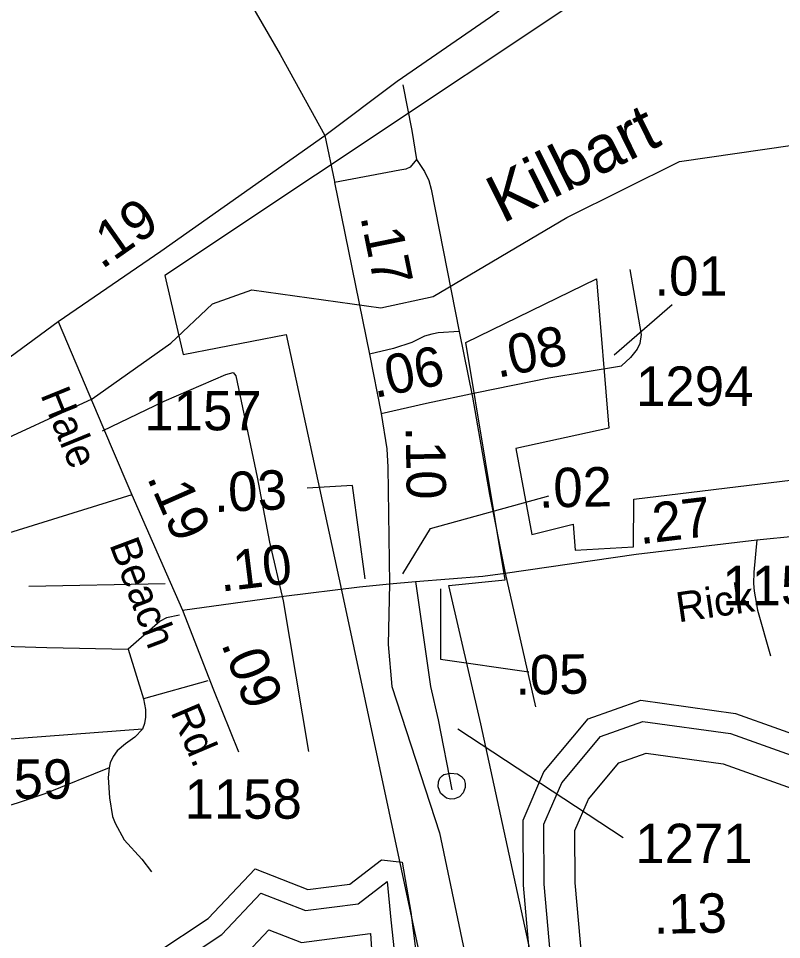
# Model space of a CAD drawing. Extents: x 2104537 to 2336408, y 34176 to 229611.
# Drawn here: x 2168604 to 2171023, y 54016 to 56935 of the extents above; entities that cross this region are included whole.
import ezdxf

# ---------------------------------------------------------------- set-up
doc = ezdxf.new("R2010")
doc.units = 0
for name, color, linetype in [('Exist Boundary Political City Limit New', 7, 'Continuous'), ('Exist Hydrographic Buffer Line', 7, 'Continuous'), ('Exist Hydrographic Creek Single Shore', 7, 'Continuous'), ('Exist Road Non-System Type 51', 7, 'Continuous'), ('Exist Road Primary NC Attributed', 7, 'Continuous'), ('Exist Road Primary NC Mileage Hundredths English Label', 7, 'Continuous'), ('Exist Road Secondary Mileage Hundredths English Label', 7, 'Continuous'), ('Exist Road Secondary Type 51 Attributed', 7, 'Continuous'), ('Exist Road Secondary Type 51 Label', 7, 'Continuous'), ('Exist Road Secondary Type 51 Number Label', 7, 'Continuous'), ('Map Preparation Boundary City Limit Buffer Line', 7, 'Continuous'), ('Old_Level_32', 7, 'Continuous')]:
    doc.layers.add(name, color=color, linetype=linetype)

msp = doc.modelspace()

# ---------------------------------------------------------------- linework, layer by layer
at = {"layer": 'Exist Boundary Political City Limit New'}
msp.add_lwpolyline([(2176257.8, 54846.6), (2173854.8, 54184.7), (2170314, 53571.9), (2170069.8, 54698.9), (2169968, 55137.6), (2170146.2, 55155.3), (2170021.5, 55907.7), (2170435.5, 56110), (2170474.8, 55636), (2170179.8, 55571.6), (2170231.5, 55299.3), (2170362.5, 55332.5), (2170368.8, 55249.4), (2170553.8, 55259.8), (2170554, 55411.4), (2171311.8, 55503.1), (2170974.8, 57391.3), (2169068.2, 56119.6), (2169126, 55869.2), (2169452.2, 55932.9), (2169628, 55123.1), (2169966.8, 53537.6)], dxfattribs=at)
at = {"layer": 'Exist Hydrographic Buffer Line'}
for points in [[(2170318.6, 53644.1), (2170270, 54190.6), (2170269.1, 54380.8), (2170325.9, 54512.4), (2170448.3, 54659.2), (2170583.2, 54707), (2170860.7, 54668.3), (2171275.3, 54520.6), (2171475.4, 54528), (2172014.2, 54766.4), (2172225.3, 54765.3), (2172465.8, 54706.7), (2172678.2, 54748.2), (2172795.6, 54838.6), (2172763.6, 55066.9), (2172705, 55237.7), (2172704, 55437.6), (2172771.6, 55612.9), (2172986, 55968.3), (2173064.5, 56033.8), (2173115.1, 56043.8)], [(2170424.2, 53568.6), (2170368.4, 54195.2), (2170367.6, 54360.7), (2170410.6, 54460.3), (2170506.6, 54575.5), (2170593.4, 54606.2), (2170837.1, 54572.2), (2171260.1, 54421.5), (2171497.9, 54430.3), (2172034.7, 54667.8), (2172213.3, 54666.9), (2172463.5, 54605.9), (2172719.9, 54656.1), (2172901, 54795.5), (2172875.4, 54978.3)], [(2168918, 53812.9), (2169247.9, 54031.6), (2169371.6, 54162.7), (2169513.1, 54107.2), (2169680.2, 54128.7), (2169772, 54199.2), (2169784.2, 54078), (2169843.5, 53526.2)], [(2169311.8, 53955.8), (2169397.6, 54046.8), (2169500.6, 54006.4), (2169719.1, 54034.5), (2169720, 54035.2), (2169759.7, 53414.5)]]:
    msp.add_lwpolyline(points, dxfattribs=at)
at = {"layer": 'Exist Hydrographic Creek Single Shore'}
for points in [[(2168488.3, 55569.1), (2168837.3, 55729.7), (2169086.3, 55905.4), (2169219.3, 56030.8), (2169343.4, 56074.3), (2169752.3, 56017.2), (2169918.4, 56053.4), (2170342.4, 56304.4), (2170699.4, 56481.2), (2171057.4, 56533.4), (2171407.4, 56543.1), (2171623.4, 56680), (2172140.3, 56591.3), (2172407.3, 56609.1), (2172739.5, 56825.8), (2172897.4, 56878.5), (2173080.5, 56861.9), (2173181.3, 56777.9), (2173206.4, 56695.4), (2173183.4, 56279.1), (2173134.4, 56204.6), (2173126.4, 56112.9)], [(2170248.3, 53694.5), (2170204.4, 54187.5), (2170203.4, 54394.2), (2170269.4, 54547.2), (2170409.5, 54715.1), (2170576.4, 54774.2), (2170876.4, 54732.3), (2171285.4, 54586.6), (2171460.3, 54593.1), (2172000.5, 54832), (2172233.4, 54830.8), (2172467.4, 54773.8), (2172650.5, 54809.7), (2172725.3, 54867.3)], [(2168873.4, 53862.1), (2169205.4, 54082.1), (2169354.3, 54240), (2169521.4, 54174.4), (2169654.2, 54191.6), (2169754.3, 54268.4), (2169820.3, 54260.5), (2169847, 54102.5), (2169909.8, 53613.5)]]:
    msp.add_lwpolyline(points, dxfattribs=at)
at = {"layer": 'Exist Road Non-System Type 51'}
for p, q in [((2169813.1, 56454.1), (2169605.7, 56414.4)), ((2170000.5, 55942.2), (2170043.4, 55734.3)), ((2170146.5, 55176.5), (2170242.7, 54753)), ((2169068.4, 55143.2), (2168636.4, 55134.8)), ((2169442.7, 55089), (2169523.4, 54611.1)), ((2168951.2, 54936.4), (2169000.3, 54778.3)), ((2169203.8, 54835.4), (2169000.3, 54778.3)), ((2168996.8, 54682.6), (2168348.8, 54633.1))]:
    msp.add_line(p, q, dxfattribs=at)
for points in [[(2169822.3, 56723.9), (2169850.7, 56579.6), (2169865.3, 56487.8)], [(2169865.3, 56487.8), (2169845.5, 56463.6), (2169831.6, 56457.6), (2169813.1, 56454.1)], [(2169865.3, 56487.8), (2169890.9, 56450.2), (2169904.1, 56421.1), (2169911.8, 56394), (2170000.5, 55942.2)], [(2170542, 56138.8), (2170577.4, 55932.7), (2170573.3, 55904.6), (2170564.4, 55886.4), (2170543.8, 55859.7), (2170515.7, 55834.1)], [(2169919.1, 55934.7), (2169914.4, 55933.7), (2169890.3, 55927.6), (2169850.5, 55907.3), (2169792.4, 55889.1), (2169716.6, 55870.5)], [(2170000.5, 55942.2), (2169934.1, 55937.9), (2169919.1, 55934.7)], [(2168869.7, 55628.3), (2169065.1, 55721.3), (2169261, 55806.2), (2169284.7, 55812.3), (2169292.7, 55802.6), (2169360.7, 55480.7), (2169399.7, 55274.9), (2169442.7, 55089)], [(2170043.4, 55734.3), (2170096.9, 55426.5), (2170146.5, 55176.5)], [(2168962.6, 55424.7), (2168523.2, 55288.5), (2168400.3, 55250.4)], [(2170943.9, 55282.5), (2170935, 55179.7), (2170933.3, 55143.6), (2170935.8, 55119.6), (2170946.8, 55060), (2170988, 54914.9)], [(2169114.7, 55043.2), (2169072.8, 55035.1), (2169053, 55024.7), (2168951.2, 54936.4)], [(2168383.2, 54950.3), (2168693.4, 54941.1), (2168951.2, 54936.4)], [(2169000.3, 54778.3), (2169006.5, 54744.4), (2169006.4, 54720.4), (2169003.4, 54700.8), (2168996.8, 54682.6)], [(2168996.8, 54682.6), (2168973, 54656.5), (2168942.8, 54636), (2168917.1, 54613.2), (2168903.6, 54595.8), (2168894, 54575.6), (2168891.7, 54559.6)], [(2168891.7, 54559.6), (2168687.7, 54476.9), (2168603.2, 54449.3), (2168414.1, 54391.3), (2168328.1, 54376.9)], [(2168891.7, 54559.6), (2168888.2, 54528.8), (2168891.9, 54464.8), (2168901.9, 54405.8), (2168910.3, 54384), (2168938.5, 54332), (2168994.8, 54270.2), (2169025.2, 54230.2)], [(2169973.5, 54543.3), (2169995.5, 54540.6), (2170008.1, 54532.5), (2170016.1, 54523.1), (2170019.8, 54510.3), (2170019.9, 54497.5), (2170013, 54480.5), (2170002.2, 54467.6), (2169986, 54461.4), (2169972.9, 54460.3), (2169960.2, 54463.8), (2169949.5, 54471.6), (2169941.5, 54480), (2169934, 54499.1), (2169935.3, 54515.8), (2169939.4, 54526.6), (2169946.4, 54534.7), (2169951.8, 54538.5), (2169973.5, 54543.3)]]:
    msp.add_lwpolyline(points, dxfattribs=at)
at = {"layer": 'Exist Road Primary NC Attributed'}
msp.add_line((2168342.7, 55689.7), (2168730, 55974.6), dxfattribs=at)
for points in [[(2169574.4, 56563.6), (2169804.2, 56735.7), (2170099.9, 56940.1), (2170550.2, 57266.2), (2170963.4, 57555.2), (2171145.6, 57685.4)], [(2168730, 55974.6), (2169054.9, 56197.6), (2169574.4, 56563.6)], [(2169574.4, 56563.6), (2169605.1, 56417.8), (2169605.7, 56414.4), (2169716.6, 55870.5), (2169753.7, 55682.8)], [(2169753.7, 55682.8), (2169771.2, 55570.6), (2169775, 55512.4), (2169780.3, 55143.4)], [(2169780.3, 55143.4), (2169775.7, 54951), (2169787.2, 54817.3), (2169938.6, 54353.6), (2170017.1, 53976.9), (2170038, 53804.3), (2170064.2, 53485.1)]]:
    msp.add_lwpolyline(points, dxfattribs=at)
at = {"layer": 'Exist Road Secondary Mileage Hundredths English Label'}
msp.add_line((2170492.1, 55868.9), (2170675.5, 56028.4), dxfattribs=at)
for points in [[(2169702.6, 55159.2), (2169662.8, 55454.2), (2169519.2, 55446.3)], [(2169822.3, 55175.1), (2169910, 55318.7), (2170284.7, 55422.3)], [(2169941.9, 55127.3), (2169941.9, 54904), (2170221, 54864.2)]]:
    msp.add_lwpolyline(points, dxfattribs=at)
at = {"layer": 'Exist Road Secondary Type 51 Attributed'}
msp.add_line((2169780.3, 55143.4), (2169862.3, 55150), dxfattribs=at)
for points in [[(2168570.8, 59389.5), (2168598.9, 59244.9), (2168639.9, 59026.9), (2168716.9, 58615.5), (2168848, 57912.2), (2168862.7, 57849.9), (2168880.8, 57795.8), (2168902.1, 57749.9), (2168936.5, 57682.7), (2169041.3, 57504), (2169254.3, 57128.6), (2169433, 56820.4), (2169574.4, 56563.6)], [(2168730, 55974.6), (2168897.2, 55577.9), (2168962.6, 55424.7), (2169072.5, 55174.6), (2169123.3, 55059.8)], [(2169753.7, 55682.8), (2169897.5, 55715.1), (2170056.6, 55749.8), (2170284.8, 55796.1), (2170515.7, 55834.1)], [(2169862.3, 55150), (2170075.6, 55167.3), (2170146.5, 55176.5), (2170562.1, 55236.7), (2170943.9, 55282.5), (2171199.6, 55307.8), (2171231.8, 55310.1), (2171460.7, 55343.8), (2171557.6, 55358.4)], [(2169862.3, 55150), (2169910.2, 54817.2), (2169934.5, 54712.4), (2169977.9, 54489.6)], [(2169123.3, 55059.8), (2169444.4, 55104.1), (2169685.3, 55133.6), (2169780.3, 55143.4)], [(2169123.3, 55059.8), (2169221.6, 54807.4), (2169301.4, 54610.2)]]:
    msp.add_lwpolyline(points, dxfattribs=at)
at = {"layer": 'Exist Road Secondary Type 51 Number Label'}
msp.add_line((2169996.7, 54683.1), (2170520.4, 54339), dxfattribs=at)
at = {"layer": 'Map Preparation Boundary City Limit Buffer Line'}
msp.add_lwpolyline([(2176257.8, 54846.6), (2173854.8, 54184.7), (2170314, 53571.9), (2170069.8, 54698.9), (2169968, 55137.6), (2170146.2, 55155.3), (2170021.5, 55907.7), (2170435.5, 56110), (2170474.8, 55636), (2170179.8, 55571.6), (2170231.5, 55299.3), (2170362.5, 55332.5), (2170368.8, 55249.4), (2170553.8, 55259.8), (2170554, 55411.4), (2171311.8, 55503.1), (2170974.8, 57391.3), (2169068.2, 56119.6), (2169126, 55869.2), (2169452.2, 55932.9), (2169628, 55123.1), (2169966.8, 53537.6)], dxfattribs=at)

# ---------------------------------------------------------------- texts
at = {"layer": 'Exist Road Primary NC Mileage Hundredths English Label'}
for s, rotation, p in [('.19', 35.168, (2168867.7, 56137.7)), ('.17', 281.5264, (2169687, 56306.4)), ('.10', 270.826, (2169831.2, 55641.5))]:
    msp.add_text(s, height=125, rotation=rotation, dxfattribs=at).set_placement(p)
at = {"layer": 'Exist Road Secondary Mileage Hundredths English Label'}
for s, rotation, p in [('.01', 359.7984, (2170619.4, 56056.7)), ('.08', 11.4568, (2170122.7, 55795.3)), ('.06', 11.3083, (2169733.2, 55731.5)), ('.03', 2.3639, (2169224.5, 55370.1)), ('.02', 1.1168, (2170253.9, 55384.2)), ('.19', 293.719, (2169009.8, 55480)), ('.27', 6.8388, (2170574.6, 55268.2)), ('.10', 6.979, (2169245.8, 55117.7)), ('.09', 291.2776, (2169245.1, 54952.9)), ('.05', 1.1168, (2170179.3, 54790.9)), ('.13', 1.1168, (2170617.9, 54033.4))]:
    msp.add_text(s, height=125, rotation=rotation, dxfattribs=at).set_placement(p)
at = {"layer": 'Exist Road Secondary Type 51 Label'}
for s, rotation, p in [('Hale', 292.1065, (2168672.3, 55742.5)), ('Beach', 290.592, (2168891.1, 55267.6)), ('Rick', 8.2468, (2170695.6, 55020.6)), ('Rd.', 292.9909, (2169084.8, 54736.6))]:
    msp.add_text(s, height=95, rotation=rotation, dxfattribs=at).set_placement(p)
at = {"layer": 'Exist Road Secondary Type 51 Number Label'}
for s, p in [('1294', (2170561.5, 55707)), ('1157', (2169002.7, 55629.4)), ('1157', (2170834.5, 55075.3)), ('1159', (2168402.5, 54461.9)), ('1158', (2169130.2, 54398.5)), ('1271', (2170559.3, 54257.7))]:
    msp.add_text(s, height=125, dxfattribs=at).set_placement(p)
at = {"layer": 'Old_Level_32'}
msp.add_text('Kilbart', height=150, rotation=26.3525, dxfattribs=at).set_placement((2170138.1, 56283.7))

doc.saveas('drawing.dxf')
